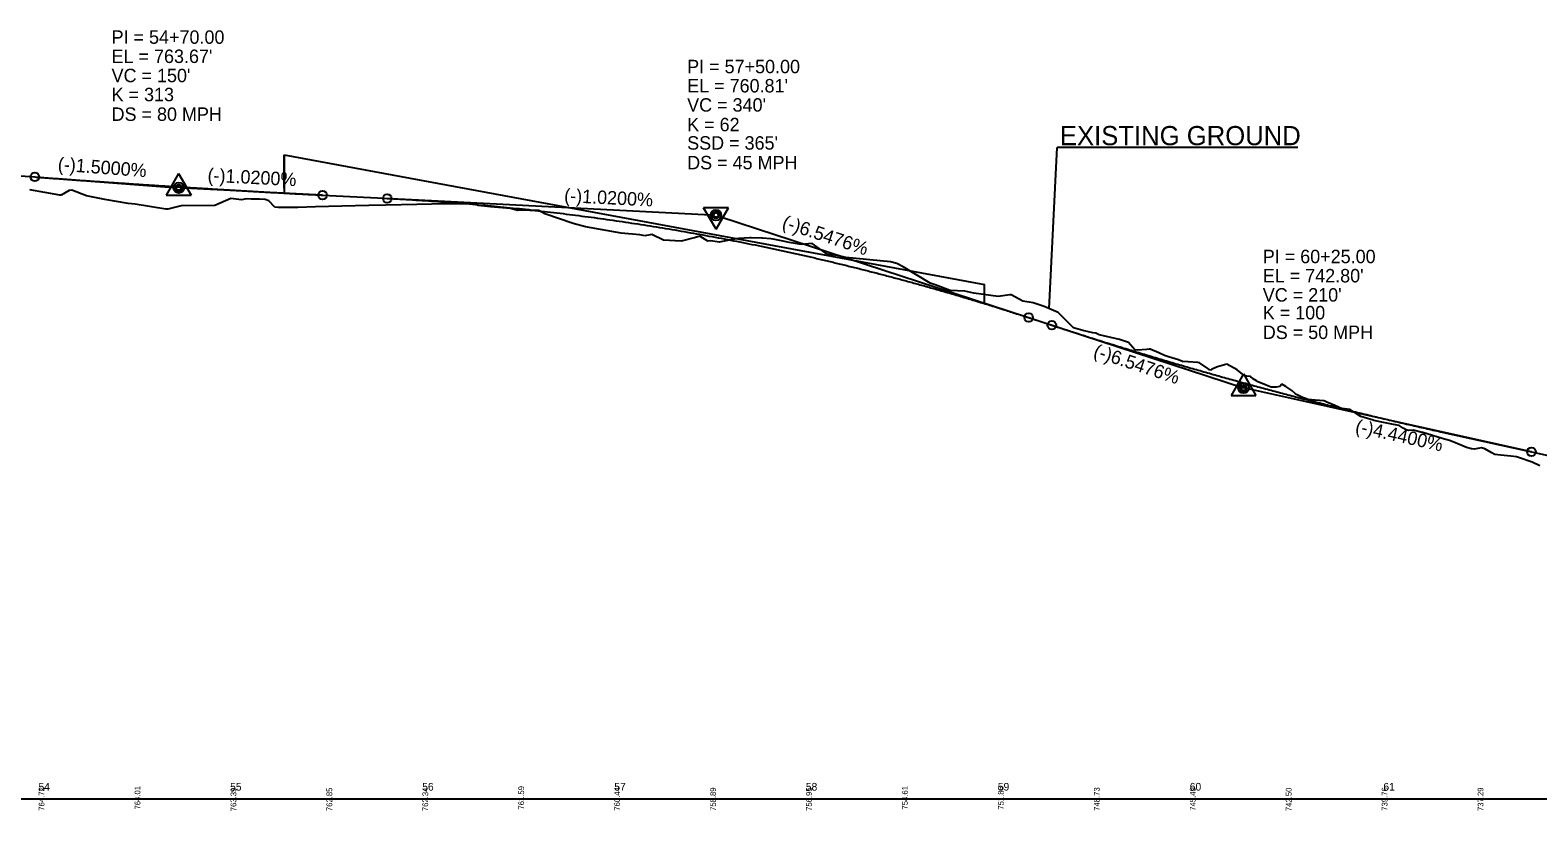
# Model space of a CAD drawing. Extents: x 1554255 to 1803987, y 659549 to 692876.
# Drawn here: x 1559186 to 1559972, y 692256 to 692662 of the extents above; entities that cross this region are included whole.
import ezdxf

# ---------------------------------------------------------------- set-up
doc = ezdxf.new("R2010")
doc.units = 0
for name, color, linetype in [('Default', 7, 'Continuous'), ('Exist Profile Cell', 7, 'Continuous'), ('Exist Vertical Profile Ground Line', 7, 'Continuous'), ('Prop PFL Text', 7, 'Continuous'), ('Prop PFL VPI Symbol CELL', 7, 'Continuous'), ('Prop Vertical Profile Curve Label', 7, 'Continuous'), ('Prop Vertical Profile Grade', 7, 'Continuous'), ('Prop Vertical Profile Grade Label', 7, 'Continuous'), ('Prop Vertical Profile Strip Grade', 7, 'Continuous'), ('Prop VPI Label', 7, 'Continuous'), ('Scratch_Level_1', 7, 'Continuous')]:
    doc.layers.add(name, color=color, linetype=linetype)

msp = doc.modelspace()

# ---------------------------------------------------------------- linework, layer by layer
at = {"layer": 'Exist Profile Cell'}
msp.add_line((1554793.69, 692261.88), (1561762.5, 692261.88), dxfattribs=at)
at = {"layer": 'Exist Vertical Profile Ground Line'}
for p, q in [((1559201.63, 692576.3), (1559186.05, 692579.05)), ((1559206.51, 692578.82), (1559202.49, 692576.28)), ((1559207.98, 692578.88), (1559206.51, 692578.82)), ((1559215.65, 692575.96), (1559207.98, 692578.88)), ((1559202.49, 692576.28), (1559201.63, 692576.3)), ((1559225.23, 692574.14), (1559215.65, 692575.96)), ((1559237.39, 692571.93), (1559225.23, 692574.14)), ((1559240.97, 692571.6), (1559237.39, 692571.93)), ((1559257.01, 692569.12), (1559240.97, 692571.6)), ((1559264.97, 692570.84), (1559257.93, 692569.02)), ((1559282.49, 692570.97), (1559264.97, 692570.84)), ((1559290.92, 692574.52), (1559282.49, 692570.97)), ((1559296.4, 692573.91), (1559290.92, 692574.52)), ((1559298.94, 692574.36), (1559296.4, 692573.91)), ((1559301.51, 692574.21), (1559298.94, 692574.36)), ((1559305.86, 692574.26), (1559301.51, 692574.21)), ((1559308.81, 692574.01), (1559305.86, 692574.26)), ((1559310.67, 692573.4), (1559308.81, 692574.01)), ((1559313.73, 692570.05), (1559310.67, 692573.4)), ((1559348.77, 692570.54), (1559335.04, 692570.18)), ((1559362.83, 692570.9), (1559348.77, 692570.54)), ((1559371.6, 692571.09), (1559362.83, 692570.9)), ((1559387.86, 692571.51), (1559371.6, 692571.09)), ((1559403.27, 692571.83), (1559387.86, 692571.51)), ((1559413.51, 692571.7), (1559403.27, 692571.83)), ((1559417.39, 692572), (1559413.51, 692571.7)), ((1559419.75, 692570.91), (1559417.39, 692572)), ((1559426.12, 692570.31), (1559419.75, 692570.91)), ((1559436.59, 692569.36), (1559426.12, 692570.31)), ((1559257.93, 692569.02), (1559257.01, 692569.12)), ((1559315.46, 692569.89), (1559313.73, 692570.05)), ((1559325.81, 692569.95), (1559315.46, 692569.89)), ((1559335.04, 692570.18), (1559325.81, 692569.95)), ((1559440.32, 692568.32), (1559436.59, 692569.36)), ((1559444.87, 692568.46), (1559440.32, 692568.32)), ((1559446.72, 692568.29), (1559444.87, 692568.46)), ((1559448.61, 692568.4), (1559446.72, 692568.29)), ((1559451.35, 692568.36), (1559448.61, 692568.4)), ((1559454.5, 692566.55), (1559451.35, 692568.36)), ((1559469.33, 692561.6), (1559454.5, 692566.55)), ((1559475.73, 692559.91), (1559469.33, 692561.6)), ((1559494.26, 692556.46), (1559475.73, 692559.91)), ((1559503.98, 692555.72), (1559494.26, 692556.46)), ((1559506.62, 692555.23), (1559503.98, 692555.72)), ((1559510.26, 692555.79), (1559506.62, 692555.23)), ((1559516.3, 692552.82), (1559510.26, 692555.79)), ((1559535.32, 692554.93), (1559532.99, 692554.33)), ((1559539.52, 692552.41), (1559535.32, 692554.93)), ((1559525.54, 692552.4), (1559516.3, 692552.82)), ((1559532.99, 692554.33), (1559525.54, 692552.4)), ((1559540.94, 692552.6), (1559539.52, 692552.41)), ((1559545.3, 692551.82), (1559540.94, 692552.6)), ((1559554.15, 692553.6), (1559545.3, 692551.82)), ((1559555.45, 692553.83), (1559554.15, 692553.6)), ((1559561.43, 692554.13), (1559555.45, 692553.83)), ((1559562.12, 692554.15), (1559561.43, 692554.13)), ((1559567.64, 692553.93), (1559562.12, 692554.15)), ((1559568.02, 692553.94), (1559567.64, 692553.93)), ((1559572.36, 692553.6), (1559568.02, 692553.94)), ((1559573.55, 692553.37), (1559572.36, 692553.6)), ((1559578.72, 692552.42), (1559573.55, 692553.37)), ((1559581.87, 692551.61), (1559578.72, 692552.42)), ((1559588.15, 692550.71), (1559581.87, 692551.61)), ((1559593.79, 692551.1), (1559588.15, 692550.71)), ((1559601.64, 692545.65), (1559593.79, 692551.1)), ((1559602.48, 692545.43), (1559601.64, 692545.65)), ((1559607.08, 692544.87), (1559602.48, 692545.43)), ((1559611.44, 692543.87), (1559607.08, 692544.87)), ((1559634.62, 692541.53), (1559611.44, 692543.87)), ((1559637.93, 692540.81), (1559634.62, 692541.53)), ((1559641.33, 692539.08), (1559637.93, 692540.81)), ((1559655.35, 692530.54), (1559641.33, 692539.08)), ((1559657.89, 692529.65), (1559655.35, 692530.54)), ((1559665.77, 692526.67), (1559657.89, 692529.65)), ((1559673.42, 692526.31), (1559665.77, 692526.67)), ((1559678.08, 692525.33), (1559673.42, 692526.31)), ((1559690.71, 692523.62), (1559678.08, 692525.33)), ((1559696.93, 692524.46), (1559690.71, 692523.62)), ((1559697.53, 692524.34), (1559696.93, 692524.46)), ((1559703.6, 692521.14), (1559697.53, 692524.34)), ((1559709.02, 692520.2), (1559703.6, 692521.14)), ((1559714.79, 692518.27), (1559709.02, 692520.2)), ((1559722.07, 692515.14), (1559714.79, 692518.27)), ((1559730.1, 692507.18), (1559722.07, 692515.14)), ((1559734.94, 692505.78), (1559730.1, 692507.18)), ((1559740.14, 692504.54), (1559734.94, 692505.78)), ((1559741.76, 692504.53), (1559740.14, 692504.54)), ((1559743.38, 692503.63), (1559741.76, 692504.53)), ((1559753.96, 692501.09), (1559743.38, 692503.63)), ((1559758.78, 692499.62), (1559753.96, 692501.09)), ((1559762.03, 692495.8), (1559758.78, 692499.62)), ((1559763.24, 692495.51), (1559762.03, 692495.8)), ((1559768.18, 692496.02), (1559763.24, 692495.51)), ((1559769.41, 692496.14), (1559768.18, 692496.02)), ((1559769.93, 692496.19), (1559769.41, 692496.14)), ((1559774.5, 692494.18), (1559769.93, 692496.19)), ((1559777.52, 692492.85), (1559774.5, 692494.18)), ((1559779.6, 692492.16), (1559777.52, 692492.85)), ((1559784.69, 692490.48), (1559779.6, 692492.16)), ((1559786.92, 692489.75), (1559784.69, 692490.48)), ((1559789.79, 692489.52), (1559786.92, 692489.75)), ((1559794.88, 692489.14), (1559789.79, 692489.52)), ((1559795.76, 692489.07), (1559794.88, 692489.14)), ((1559799.97, 692485.96), (1559795.76, 692489.07)), ((1559800.89, 692485.29), (1559799.97, 692485.96)), ((1559801.37, 692485.14), (1559800.89, 692485.29)), ((1559801.96, 692485.52), (1559801.37, 692485.14)), ((1559804.6, 692486.76), (1559801.96, 692485.52)), ((1559805.07, 692486.9), (1559804.6, 692486.76)), ((1559809.95, 692488.3), (1559805.07, 692486.9)), ((1559815.29, 692485.41), (1559809.95, 692488.3)), ((1559818.99, 692482.45), (1559815.29, 692485.41)), ((1559819.54, 692482.23), (1559818.99, 692482.45)), ((1559820.35, 692482.12), (1559819.54, 692482.23)), ((1559822.29, 692481.85), (1559820.35, 692482.12)), ((1559823.77, 692480.59), (1559822.29, 692481.85)), ((1559825.45, 692479.58), (1559823.77, 692480.59)), ((1559825.84, 692479.34), (1559825.45, 692479.58)), ((1559830.54, 692477.4), (1559825.84, 692479.34)), ((1559833.02, 692476.38), (1559830.54, 692477.4)), ((1559835.2, 692476.26), (1559833.02, 692476.38)), ((1559835.63, 692476.33), (1559835.2, 692476.26)), ((1559837.54, 692476.67), (1559835.63, 692476.33)), ((1559838.7, 692477.95), (1559837.54, 692476.67)), ((1559840.73, 692476.63), (1559838.7, 692477.95)), ((1559843.8, 692474.64), (1559840.73, 692476.63)), ((1559845.82, 692472.86), (1559843.8, 692474.64)), ((1559846.29, 692472.45), (1559845.82, 692472.86)), ((1559849.45, 692470.96), (1559846.29, 692472.45)), ((1559850.92, 692470.35), (1559849.45, 692470.96)), ((1559852.22, 692469.81), (1559850.92, 692470.35)), ((1559856.01, 692469.53), (1559852.22, 692469.81)), ((1559860.58, 692469.19), (1559856.01, 692469.53)), ((1559861.11, 692468.95), (1559860.58, 692469.19)), ((1559862.12, 692468.5), (1559861.11, 692468.95)), ((1559866.2, 692466.73), (1559862.12, 692468.5)), ((1559870.07, 692465.07), (1559866.2, 692466.73)), ((1559871.29, 692464.94), (1559870.07, 692465.07)), ((1559874.27, 692464.63), (1559871.29, 692464.94)), ((1559876.39, 692463.21), (1559874.27, 692464.63)), ((1559879.72, 692461), (1559876.39, 692463.21)), ((1559881.48, 692460.47), (1559879.72, 692461)), ((1559886.26, 692459.05), (1559881.48, 692460.47)), ((1559886.58, 692458.99), (1559886.26, 692459.05)), ((1559891.67, 692457.95), (1559886.58, 692458.99)), ((1559896.77, 692456.92), (1559891.67, 692457.95)), ((1559899.78, 692456.32), (1559896.77, 692456.92)), ((1559901.86, 692455.03), (1559899.78, 692456.32)), ((1559903.36, 692454.1), (1559901.86, 692455.03)), ((1559904.56, 692453.75), (1559903.36, 692454.1)), ((1559907.05, 692453.97), (1559904.56, 692453.75)), ((1559911.73, 692452.71), (1559907.05, 692453.97)), ((1559912.05, 692452.61), (1559911.73, 692452.71)), ((1559917.14, 692451.15), (1559912.05, 692452.61)), ((1559919.44, 692450.5), (1559917.14, 692451.15)), ((1559922.24, 692449.63), (1559919.44, 692450.5)), ((1559925.98, 692448.47), (1559922.24, 692449.63)), ((1559927.33, 692447.92), (1559925.98, 692448.47)), ((1559932.43, 692445.86), (1559927.33, 692447.92)), ((1559934.85, 692444.89), (1559932.43, 692445.86)), ((1559937.52, 692444.26), (1559934.85, 692444.89)), ((1559942.68, 692444.71), (1559938.84, 692443.96)), ((1559944.43, 692444.18), (1559942.68, 692444.71)), ((1559938.84, 692443.96), (1559937.52, 692444.26)), ((1559947.71, 692442.32), (1559944.43, 692444.18)), ((1559949.6, 692441.26), (1559947.71, 692442.32)), ((1559952.8, 692440.89), (1559949.6, 692441.26)), ((1559957.9, 692440.31), (1559952.8, 692440.89)), ((1559961, 692439.97), (1559957.9, 692440.31)), ((1559962.99, 692439.28), (1559961, 692439.97)), ((1559968.09, 692437.53), (1559962.99, 692439.28)), ((1559969.02, 692437.21), (1559968.09, 692437.53)), ((1559973.18, 692435.26), (1559969.02, 692437.21))]:
    msp.add_line(p, q, dxfattribs=at)
at = {"layer": 'Prop PFL Text'}
for p in [(1559717.42, 692517.14), (1559846.9, 692601.15)]:
    msp.add_line(p, (1559721.59, 692601.15), dxfattribs=at)
at = {"layer": 'Prop PFL VPI Symbol CELL'}
for p, q in [((1559263.64, 692587.55), (1559257.19, 692576.35)), ((1559263.64, 692587.55), (1559270.14, 692576.35)), ((1559257.19, 692576.35), (1559270.14, 692576.35)), ((1559543.74, 692558.57), (1559537.24, 692569.77)), ((1559550.19, 692569.77), (1559537.24, 692569.77)), ((1559543.74, 692558.57), (1559550.19, 692569.77)), ((1559818.64, 692483.24), (1559812.19, 692472.04)), ((1559818.64, 692483.24), (1559825.14, 692472.04)), ((1559812.19, 692472.04), (1559825.14, 692472.04))]:
    msp.add_line(p, q, dxfattribs=at)
for centre, radius in [((1559263.65, 692580.07), 1.75), ((1559263.65, 692580.07), 1.2), ((1559543.73, 692566.05), 1.75), ((1559543.73, 692566.05), 1.2), ((1559818.65, 692475.76), 1.75), ((1559818.65, 692475.76), 1.2)]:
    msp.add_circle(centre, radius, dxfattribs=at)
at = {"layer": 'Prop Vertical Profile Curve Label'}
for centre in [(1559188.69, 692585.83), (1559338.69, 692576.38), (1559372.4, 692574.66), (1559706.68, 692512.56), (1559718.78, 692508.6), (1559968.69, 692442.59)]:
    msp.add_circle(centre, 2.25, dxfattribs=at)
at = {"layer": 'Prop Vertical Profile Grade'}
for p, q in [((1559126.19, 692590.51), (1559188.69, 692585.83)), ((1559338.69, 692576.38), (1559388.69, 692573.83)), ((1559706.68, 692512.56), (1559727.73, 692505.67)), ((1559921.32, 692453.11), (1559968.69, 692442.59)), ((1559968.69, 692442.59), (1560038.69, 692427.05))]:
    msp.add_line(p, q, dxfattribs=at)
for points in [[(1559188.69, 692585.83), (1559191.69, 692585.6), (1559194.69, 692585.38), (1559197.69, 692585.16), (1559200.69, 692584.94), (1559203.69, 692584.72), (1559206.69, 692584.5), (1559209.69, 692584.29), (1559212.69, 692584.07), (1559215.69, 692583.86), (1559218.69, 692583.65), (1559221.69, 692583.44), (1559224.69, 692583.23), (1559227.69, 692583.02), (1559230.69, 692582.82), (1559233.69, 692582.61), (1559236.69, 692582.41), (1559239.69, 692582.21), (1559242.69, 692582.01), (1559245.69, 692581.81), (1559248.69, 692581.62), (1559251.69, 692581.42), (1559254.69, 692581.23), (1559257.69, 692581.03), (1559260.69, 692580.84), (1559263.69, 692580.65), (1559266.69, 692580.46), (1559269.69, 692580.28), (1559272.69, 692580.09), (1559275.69, 692579.91), (1559278.69, 692579.73), (1559281.69, 692579.54), (1559284.69, 692579.36), (1559287.69, 692579.19), (1559290.69, 692579.01), (1559293.69, 692578.83), (1559296.69, 692578.66), (1559299.69, 692578.49), (1559302.69, 692578.32), (1559305.69, 692578.15), (1559308.69, 692577.98), (1559311.69, 692577.81), (1559314.69, 692577.65), (1559317.69, 692577.48), (1559320.69, 692577.32), (1559323.69, 692577.16), (1559326.69, 692577), (1559329.69, 692576.84), (1559332.69, 692576.69), (1559335.69, 692576.53), (1559338.69, 692576.38)], [(1559372.4, 692574.66), (1559378.99, 692574.31), (1559385.57, 692573.92), (1559392.14, 692573.5), (1559398.71, 692573.05), (1559405.27, 692572.57), (1559411.82, 692572.05), (1559418.37, 692571.5), (1559424.91, 692570.91), (1559431.45, 692570.3), (1559437.98, 692569.65), (1559444.5, 692568.97), (1559451.02, 692568.25), (1559457.53, 692567.5), (1559464.03, 692566.72), (1559470.53, 692565.9), (1559477.02, 692565.06), (1559483.51, 692564.18), (1559489.99, 692563.26), (1559496.47, 692562.32), (1559502.93, 692561.34), (1559509.4, 692560.32), (1559515.85, 692559.28), (1559522.3, 692558.2), (1559528.75, 692557.09), (1559535.18, 692555.94), (1559541.62, 692554.77), (1559548.04, 692553.56), (1559554.46, 692552.31), (1559560.87, 692551.03), (1559567.28, 692549.73), (1559573.68, 692548.38), (1559580.08, 692547.01), (1559586.46, 692545.6), (1559592.85, 692544.16), (1559599.22, 692542.68), (1559605.59, 692541.17), (1559611.96, 692539.63), (1559618.32, 692538.06), (1559624.67, 692536.45), (1559631.01, 692534.81), (1559637.35, 692533.14), (1559643.69, 692531.43), (1559650.01, 692529.7), (1559656.34, 692527.92), (1559662.65, 692526.12), (1559668.96, 692524.28), (1559675.26, 692522.41), (1559681.56, 692520.51), (1559687.85, 692518.57), (1559694.13, 692516.6), (1559700.41, 692514.6), (1559706.68, 692512.56)], [(1559718.78, 692508.6), (1559722.63, 692507.34), (1559726.47, 692506.1), (1559730.32, 692504.86), (1559734.17, 692503.63), (1559738.02, 692502.4), (1559741.88, 692501.18), (1559745.73, 692499.97), (1559749.59, 692498.77), (1559753.45, 692497.57), (1559757.31, 692496.39), (1559761.18, 692495.21), (1559765.04, 692494.03), (1559768.91, 692492.87), (1559772.78, 692491.71), (1559776.65, 692490.56), (1559780.52, 692489.41), (1559784.4, 692488.27), (1559788.28, 692487.14), (1559792.16, 692486.02), (1559796.04, 692484.91), (1559799.92, 692483.8), (1559803.81, 692482.7), (1559807.7, 692481.61), (1559811.59, 692480.52), (1559815.48, 692479.44), (1559819.37, 692478.37), (1559823.27, 692477.31), (1559827.17, 692476.25), (1559831.07, 692475.2), (1559834.97, 692474.16), (1559838.87, 692473.13), (1559842.78, 692472.1), (1559846.69, 692471.08), (1559850.6, 692470.07), (1559854.51, 692469.07), (1559858.42, 692468.07), (1559862.34, 692467.08), (1559866.26, 692466.1), (1559870.18, 692465.12), (1559874.1, 692464.15), (1559878.02, 692463.19), (1559881.95, 692462.24), (1559885.88, 692461.29), (1559889.81, 692460.35), (1559893.74, 692459.42), (1559897.67, 692458.5), (1559901.61, 692457.58), (1559905.55, 692456.67), (1559909.49, 692455.77), (1559913.43, 692454.88), (1559917.37, 692453.99), (1559921.32, 692453.11)]]:
    msp.add_spline(points, degree=3, dxfattribs=at)
at = {"layer": 'Prop VPI Label'}
for p, q in [((1559188.69, 692585.83), (1559260.95, 692580.41)), ((1559338.69, 692576.38), (1559266.43, 692580.06)), ((1559388.69, 692573.83), (1559540.94, 692566.06)), ((1559546.3, 692565.07), (1559818.69, 692475.89)), ((1559968.69, 692442.59), (1559818.69, 692475.89))]:
    msp.add_line(p, q, dxfattribs=at)
for centre in [(1559263.69, 692580.2), (1559543.69, 692565.92), (1559818.69, 692475.89)]:
    msp.add_circle(centre, 2.75, dxfattribs=at)
at = {"layer": 'Scratch_Level_1'}
for p, q in [((1559318.69, 692579.93), (1559318.69, 692597.27)), ((1559318.69, 692597.27), (1559318.69, 692577.43)), ((1559318.69, 692597.27), (1559683.67, 692529.86)), ((1559683.63, 692519.87), (1559683.63, 692529.87))]:
    msp.add_line(p, q, dxfattribs=at)

# ---------------------------------------------------------------- texts
at = {"layer": 'Default'}
for s, p in [('54', (1559190.6, 692266.13)), ('55', (1559290.49, 692266.13)), ('56', (1559390.6, 692266.13)), ('57', (1559490.7, 692266.13)), ('58', (1559590.55, 692266.13)), ('59', (1559690.6, 692266.13)), ('60', (1559790.66, 692266.13)), ('61', (1559891.55, 692266.13))]:
    msp.add_text(s, height=4, dxfattribs=at).set_placement(p)
at = {"layer": 'Prop PFL Text'}
msp.add_text('EXISTING GROUND', height=10, rotation=360, dxfattribs=at).set_placement((1559722.94, 692602.37))
at = {"layer": 'Prop Vertical Profile Curve Label'}
for s, p in [("VC = 150'", (1559228.69, 692635.2)), ('K = 313', (1559228.69, 692625.29)), ("VC = 340'", (1559528.69, 692619.86)), ('DS = 80 MPH', (1559228.69, 692615.05)), ('K = 62', (1559528.69, 692609.63)), ("SSD = 365'", (1559528.69, 692600.05)), ('DS = 45 MPH', (1559528.69, 692589.8)), ("VC = 210'", (1559828.69, 692520.9)), ('K = 100', (1559828.69, 692511.64)), ('DS = 50 MPH', (1559828.69, 692501.4))]:
    msp.add_text(s, height=7, dxfattribs=at).set_placement(p)
at = {"layer": 'Prop Vertical Profile Grade Label'}
for s, rotation, p in [('(-)1.5000%', 355.71085, (1559200.49, 692589.14)), ('(-)1.0200%', 357.08044, (1559278.59, 692583.37)), ('(-)1.0200%', 357.08044, (1559464.45, 692572.76)), ('(-)6.5476%', 341.73711, (1559577.69, 692559.37)), ('(-)6.5476%', 341.73711, (1559739.95, 692492.27)), ('(-)4.4400%', 347.48333, (1559876.52, 692452.81))]:
    msp.add_text(s, height=7, rotation=rotation, dxfattribs=at).set_placement(p)
at = {"layer": 'Prop Vertical Profile Strip Grade'}
for s, p in [('764.72', (1559193.69, 692255.65)), ('764.01', (1559243.69, 692256.28)), ('763.39', (1559293.69, 692255.38)), ('762.85', (1559343.69, 692255.44)), ('762.34', (1559393.69, 692255.41)), ('761.59', (1559443.69, 692256.23)), ('760.44', (1559493.69, 692255.67)), ('758.89', (1559543.69, 692255.52)), ('756.95', (1559593.69, 692255.54)), ('754.61', (1559643.69, 692256.23)), ('751.86', (1559693.69, 692256.18)), ('748.73', (1559743.69, 692255.58)), ('745.49', (1559793.69, 692255.62)), ('742.50', (1559843.69, 692255.43)), ('739.76', (1559893.69, 692255.62)), ('737.29', (1559943.69, 692255.48))]:
    msp.add_text(s, height=3, rotation=90, dxfattribs=at).set_placement(p)
at = {"layer": 'Prop VPI Label'}
for s, p in [('PI = 54+70.00', (1559228.69, 692655.2)), ("EL = 763.67'", (1559228.69, 692645.2)), ('PI = 57+50.00', (1559528.69, 692639.86)), ("EL = 760.81'", (1559528.69, 692629.86)), ('PI = 60+25.00', (1559828.69, 692540.9)), ("EL = 742.80'", (1559828.69, 692530.9))]:
    msp.add_text(s, height=7, dxfattribs=at).set_placement(p)

doc.saveas('drawing.dxf')
